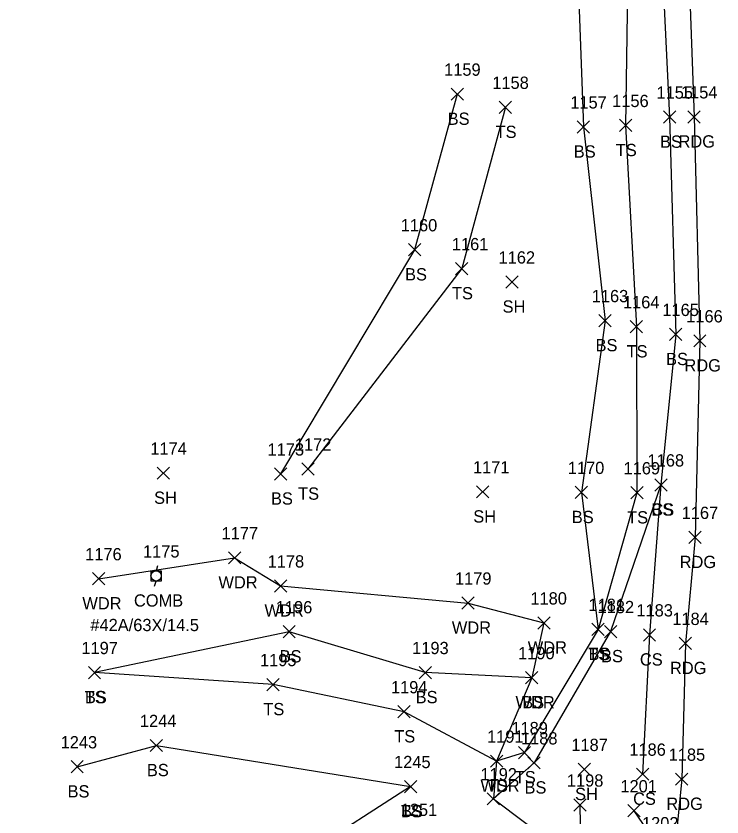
# Model space of a CAD drawing. Extents: x 1678553 to 1680768, y 787260 to 792325.
# Drawn here: x 1678586 to 1678701.1, y 787588.2 to 787718.8 of the extents above; entities that cross this region are included whole.
import ezdxf

# ---------------------------------------------------------------- set-up
doc = ezdxf.new("R2010")
doc.units = 0
for name, color, linetype in [('L_A', 7, 'Continuous'), ('L_I', 7, 'Continuous'), ('L_TIC', 7, 'Continuous'), ('LAWA', 7, 'Continuous'), ('LELB', 7, 'Continuous'), ('P_A', 7, 'Continuous'), ('P_I', 7, 'Continuous'), ('P_TIC', 7, 'Continuous'), ('PEU', 7, 'Continuous'), ('R_I', 7, 'Continuous'), ('R_TIC', 7, 'Continuous'), ('RGR', 7, 'Continuous'), ('U_A', 7, 'Continuous'), ('U_C', 7, 'Continuous'), ('U_I', 7, 'Continuous'), ('UP', 7, 'Continuous')]:
    doc.layers.add(name, color=color, linetype=linetype)

msp = doc.modelspace()

# ---------------------------------------------------------------- linework, layer by layer
at = {"layer": 'L_TIC'}
for points in [[(1678656.91, 787705.05), (1678658.91, 787707.05)], [(1678658.91, 787705.05), (1678656.91, 787707.05)], [(1678664.76, 787702.91), (1678666.76, 787704.91)], [(1678666.76, 787702.91), (1678664.76, 787704.91)], [(1678691.52, 787701.31), (1678693.52, 787703.31)], [(1678693.52, 787701.31), (1678691.52, 787703.31)], [(1678677.47, 787699.71), (1678679.47, 787701.71)], [(1678679.47, 787699.71), (1678677.47, 787701.71)], [(1678684.35, 787699.95), (1678686.35, 787701.95)], [(1678686.35, 787699.95), (1678684.35, 787701.95)], [(1678649.97, 787679.69), (1678651.97, 787681.69)], [(1678651.97, 787679.69), (1678649.97, 787681.69)], [(1678657.65, 787676.61), (1678659.65, 787678.61)], [(1678659.65, 787676.61), (1678657.65, 787678.61)], [(1678665.82, 787674.44), (1678667.82, 787676.44)], [(1678667.82, 787674.44), (1678665.82, 787676.44)], [(1678681.02, 787668.14), (1678683.02, 787670.14)], [(1678683.02, 787668.14), (1678681.02, 787670.14)], [(1678686.11, 787667.14), (1678688.11, 787669.14)], [(1678688.11, 787667.14), (1678686.11, 787669.14)], [(1678692.52, 787665.89), (1678694.52, 787667.89)], [(1678694.52, 787665.89), (1678692.52, 787667.89)], [(1678609.02, 787643.28), (1678611.02, 787645.28)], [(1678611.02, 787643.28), (1678609.02, 787645.28)], [(1678628.12, 787643.15), (1678630.12, 787645.15)], [(1678630.12, 787643.15), (1678628.12, 787645.15)], [(1678632.57, 787643.95), (1678634.57, 787645.95)], [(1678634.57, 787643.95), (1678632.57, 787645.95)], [(1678690.12, 787641.36), (1678692.12, 787643.36)], [(1678692.12, 787641.36), (1678690.12, 787643.36)], [(1678690.12, 787641.36), (1678692.12, 787643.36)], [(1678692.12, 787641.36), (1678690.12, 787643.36)], [(1678661.04, 787640.23), (1678663.04, 787642.23)], [(1678663.04, 787640.23), (1678661.04, 787642.23)], [(1678677.15, 787640.14), (1678679.15, 787642.14)], [(1678679.15, 787640.14), (1678677.15, 787642.14)], [(1678686.2, 787640.08), (1678688.2, 787642.08)], [(1678688.2, 787640.08), (1678686.2, 787642.08)], [(1678620.63, 787629.48), (1678622.63, 787631.48)], [(1678622.63, 787629.48), (1678620.63, 787631.48)], [(1678598.45, 787626.07), (1678600.45, 787628.07)], [(1678600.45, 787626.07), (1678598.45, 787628.07)], [(1678628.13, 787624.9), (1678630.13, 787626.9)], [(1678630.13, 787624.9), (1678628.13, 787626.9)], [(1678658.68, 787622.11), (1678660.68, 787624.11)], [(1678660.68, 787622.11), (1678658.68, 787624.11)], [(1678671.05, 787618.87), (1678673.05, 787620.87)], [(1678673.05, 787618.87), (1678671.05, 787620.87)], [(1678629.52, 787617.43), (1678631.52, 787619.43)], [(1678631.52, 787617.43), (1678629.52, 787619.43)], [(1678679.87, 787617.81), (1678681.87, 787619.81)], [(1678681.87, 787617.81), (1678679.87, 787619.81)], [(1678679.87, 787617.81), (1678681.87, 787619.81)], [(1678681.87, 787617.81), (1678679.87, 787619.81)], [(1678681.92, 787617.46), (1678683.92, 787619.46)], [(1678683.92, 787617.46), (1678681.92, 787619.46)], [(1678688.25, 787616.92), (1678690.25, 787618.92)], [(1678690.25, 787616.92), (1678688.25, 787618.92)], [(1678597.79, 787610.78), (1678599.79, 787612.78)], [(1678599.79, 787610.78), (1678597.79, 787612.78)], [(1678597.79, 787610.78), (1678599.79, 787612.78)], [(1678599.79, 787610.78), (1678597.79, 787612.78)], [(1678651.7, 787610.78), (1678653.7, 787612.78)], [(1678653.7, 787610.78), (1678651.7, 787612.78)], [(1678669.06, 787609.94), (1678671.06, 787611.94)], [(1678671.06, 787609.94), (1678669.06, 787611.94)], [(1678669.06, 787609.94), (1678671.06, 787611.94)], [(1678671.06, 787609.94), (1678669.06, 787611.94)], [(1678626.9, 787608.82), (1678628.9, 787610.82)], [(1678628.9, 787608.82), (1678626.9, 787610.82)], [(1678648.24, 787604.39), (1678650.24, 787606.39)], [(1678650.24, 787604.39), (1678648.24, 787606.39)], [(1678607.89, 787598.89), (1678609.89, 787600.89)], [(1678609.89, 787598.89), (1678607.89, 787600.89)], [(1678667.88, 787597.73), (1678669.88, 787599.73)], [(1678669.88, 787597.73), (1678667.88, 787599.73)], [(1678663.34, 787596.34), (1678665.34, 787598.34)], [(1678665.34, 787596.34), (1678663.34, 787598.34)], [(1678663.34, 787596.34), (1678665.34, 787598.34)], [(1678665.34, 787596.34), (1678663.34, 787598.34)], [(1678669.44, 787596.06), (1678671.44, 787598.06)], [(1678671.44, 787596.06), (1678669.44, 787598.06)], [(1678594.96, 787595.42), (1678596.96, 787597.42)], [(1678596.96, 787595.42), (1678594.96, 787597.42)], [(1678677.63, 787594.99), (1678679.63, 787596.99)], [(1678679.63, 787594.99), (1678677.63, 787596.99)], [(1678687.14, 787594.22), (1678689.14, 787596.22)], [(1678689.14, 787594.22), (1678687.14, 787596.22)], [(1678649.31, 787592.2), (1678651.31, 787594.2)], [(1678651.31, 787592.2), (1678649.31, 787594.2)], [(1678649.31, 787592.2), (1678651.31, 787594.2)], [(1678651.31, 787592.2), (1678649.31, 787594.2)], [(1678662.82, 787590.2), (1678664.82, 787592.2)], [(1678664.82, 787590.2), (1678662.82, 787592.2)], [(1678662.82, 787590.2), (1678664.82, 787592.2)], [(1678664.82, 787590.2), (1678662.82, 787592.2)], [(1678676.92, 787589.19), (1678678.92, 787591.19)], [(1678678.92, 787589.19), (1678676.92, 787591.19)]]:
    msp.add_lwpolyline(points, dxfattribs=at)
at = {"layer": 'LAWA'}
msp.add_lwpolyline([(1678599.45, 787627.07), (1678621.63, 787630.48), (1678629.13, 787625.9), (1678659.68, 787623.11), (1678672.05, 787619.87), (1678670.06, 787610.94), (1678664.34, 787597.34), (1678663.82, 787591.2), (1678674.57, 787583.12), (1678678.14, 787577.87), (1678672.71, 787567.7), (1678658.82, 787557.15), (1678637.9, 787553.69), (1678611.83, 787542.76), (1678587.07, 787526.57)], dxfattribs=at)
at = {"layer": 'LELB'}
for points in [[(1678682.79, 787833.91), (1678680.06, 787797.95), (1678684.41, 787774.01), (1678685.93, 787741.44), (1678685.35, 787700.95), (1678687.11, 787668.14), (1678687.2, 787641.08), (1678680.87, 787618.81), (1678668.88, 787598.73), (1678664.34, 787597.34), (1678649.24, 787605.39), (1678627.9, 787609.82), (1678598.79, 787611.78)], [(1678679.85, 787777.76), (1678676.94, 787743.26), (1678678.47, 787700.71), (1678682.02, 787669.14), (1678678.15, 787641.14), (1678680.87, 787618.81)], [(1678688.43, 787773.81), (1678690.64, 787740.5), (1678692.52, 787702.31), (1678693.52, 787666.89), (1678691.12, 787642.36), (1678682.92, 787618.46), (1678670.44, 787597.06), (1678663.82, 787591.2)], [(1678657.91, 787706.05), (1678650.97, 787680.69), (1678629.12, 787644.15)], [(1678665.76, 787703.91), (1678658.65, 787677.61), (1678633.57, 787644.95)], [(1678691.12, 787642.36), (1678689.25, 787617.92), (1678688.14, 787595.22)], [(1678670.06, 787610.94), (1678652.7, 787611.78), (1678630.52, 787618.43), (1678598.79, 787611.78)], [(1678595.96, 787596.42), (1678608.89, 787599.89), (1678650.31, 787593.2)], [(1678650.31, 787593.2), (1678633.3, 787582.25), (1678625.84, 787572.53), (1678610.05, 787567.92), (1678586, 787548.35)], [(1678677.92, 787590.19), (1678678.14, 787577.87), (1678684.37, 787570.24), (1678686.4, 787565.08)]]:
    msp.add_lwpolyline(points, dxfattribs=at)
at = {"layer": 'P_TIC'}
for points in [[(1678695.51, 787701.35), (1678697.51, 787703.35)], [(1678697.51, 787701.35), (1678695.51, 787703.35)], [(1678696.46, 787664.85), (1678698.46, 787666.85)], [(1678698.46, 787664.85), (1678696.46, 787666.85)], [(1678695.68, 787632.81), (1678697.68, 787634.81)], [(1678697.68, 787632.81), (1678695.68, 787634.81)], [(1678694.1, 787615.53), (1678696.1, 787617.53)], [(1678696.1, 787615.53), (1678694.1, 787617.53)], [(1678693.51, 787593.4), (1678695.51, 787595.4)], [(1678695.51, 787593.4), (1678693.51, 787595.4)]]:
    msp.add_lwpolyline(points, dxfattribs=at)
at = {"layer": 'PEU'}
msp.add_lwpolyline([(1678689.06, 787834.79), (1678688.67, 787796.64), (1678691.65, 787771.51), (1678695.2, 787739.73), (1678696.51, 787702.35), (1678697.46, 787665.85), (1678696.68, 787633.81), (1678695.1, 787616.53), (1678694.51, 787594.4), (1678691.17, 787560.92)], dxfattribs=at)
at = {"layer": 'R_TIC'}
for points in [[(1678685.71, 787588.25), (1678687.71, 787590.25)], [(1678687.71, 787588.25), (1678685.71, 787590.25)]]:
    msp.add_lwpolyline(points, dxfattribs=at)
at = {"layer": 'RGR'}
msp.add_lwpolyline([(1678686.71, 787589.25), (1678690.81, 787583.23), (1678691.72, 787577.16), (1678690.18, 787561.7)], dxfattribs=at)
at = {"layer": 'UP'}
for p, q in [((1678608, 787626.7), (1678608, 787628.37)), ((1678608, 787628.37), (1678609.66, 787628.37)), ((1678609.08, 787629.2), (1678608.83, 787628.37)), ((1678609.66, 787628.37), (1678609.66, 787626.7)), ((1678608.83, 787627.53), (1678608.83, 787627.53)), ((1678609.66, 787626.7), (1678608, 787626.7)), ((1678608.58, 787625.87), (1678608.83, 787626.7))]:
    msp.add_line(p, q, dxfattribs=at)
msp.add_circle((1678608.83, 787627.53), 0.833, dxfattribs=at)

# ---------------------------------------------------------------- texts
at = {"layer": 'L_A'}
for s, p in [('BS', (1678656.36, 787701.05)), ('TS', (1678664.17, 787698.91)), ('BS', (1678690.96, 787697.31)), ('BS', (1678676.91, 787695.71)), ('TS', (1678683.76, 787695.95)), ('BS', (1678649.41, 787675.69)), ('TS', (1678657.06, 787672.61)), ('SH', (1678665.31, 787670.44)), ('BS', (1678680.46, 787664.14)), ('TS', (1678685.52, 787663.14)), ('BS', (1678691.96, 787661.89)), ('SH', (1678608.5, 787639.28)), ('BS', (1678627.56, 787639.15)), ('TS', (1678631.98, 787639.95)), ('CS', (1678689.56, 787637.36)), ('BS', (1678689.56, 787637.36)), ('SH', (1678660.53, 787636.23)), ('BS', (1678676.59, 787636.14)), ('TS', (1678685.61, 787636.08)), ('WDR', (1678618.99, 787625.48)), ('WDR', (1678596.81, 787622.07)), ('WDR', (1678626.5, 787620.9)), ('WDR', (1678657.04, 787618.11)), ('WDR', (1678669.41, 787614.87)), ('BS', (1678628.96, 787613.43)), ('TS', (1678679.27, 787613.81)), ('BS', (1678679.31, 787613.81)), ('BS', (1678681.36, 787613.46)), ('CS', (1678687.69, 787612.92)), ('TS', (1678597.2, 787606.78)), ('BS', (1678597.23, 787606.78)), ('BS', (1678651.14, 787606.78)), ('WDR', (1678667.42, 787605.94)), ('BS', (1678668.5, 787605.94)), ('TS', (1678626.31, 787604.82)), ('TS', (1678647.65, 787600.39)), ('BS', (1678607.33, 787594.89)), ('TS', (1678667.29, 787593.73)), ('WDR', (1678661.7, 787592.34)), ('TS', (1678662.75, 787592.34)), ('BS', (1678668.88, 787592.06)), ('BS', (1678594.4, 787591.42)), ('SH', (1678677.12, 787590.99)), ('CS', (1678686.58, 787590.22)), ('TS', (1678648.72, 787588.2)), ('BS', (1678648.75, 787588.2))]:
    msp.add_text(s, height=2, dxfattribs=at).set_placement(p)
at = {"layer": 'L_I'}
for s, p in [('1159', (1678655.78, 787709.05)), ('1158', (1678663.63, 787706.91)), ('1155', (1678690.39, 787705.31)), ('1157', (1678676.34, 787703.71)), ('1156', (1678683.17, 787703.95)), ('1160', (1678648.71, 787683.69)), ('1161', (1678657.04, 787680.61)), ('1162', (1678664.65, 787678.44)), ('1163', (1678679.84, 787672.14)), ('1164', (1678684.93, 787671.14)), ('1165', (1678691.35, 787669.89)), ('1174', (1678607.89, 787647.28)), ('1173', (1678627, 787647.15)), ('1172', (1678631.45, 787647.95)), ('1168', (1678688.94, 787645.36)), ('1168', (1678688.94, 787645.36)), ('1171', (1678660.48, 787644.23)), ('1170', (1678675.94, 787644.14)), ('1169', (1678685.02, 787644.08)), ('1177', (1678619.5, 787633.48)), ('1176', (1678597.27, 787630.07)), ('1178', (1678627.01, 787628.9)), ('1179', (1678657.55, 787626.11)), ('1180', (1678669.84, 787622.87)), ('1196', (1678628.34, 787621.43)), ('1181', (1678679.31, 787621.81)), ('1181', (1678679.31, 787621.81)), ('1182', (1678680.79, 787621.46)), ('1183', (1678687.12, 787620.92)), ('1197', (1678596.66, 787614.78)), ('1197', (1678596.66, 787614.78)), ('1193', (1678650.57, 787614.78)), ('1190', (1678667.84, 787613.94)), ('1190', (1678667.84, 787613.94)), ('1195', (1678625.77, 787612.82)), ('1194', (1678647.11, 787608.39)), ('1244', (1678606.19, 787602.89)), ('1189', (1678666.74, 787601.73)), ('1191', (1678662.78, 787600.34)), ('1191', (1678662.78, 787600.34)), ('1188', (1678668.31, 787600.06)), ('1243', (1678593.27, 787599.42)), ('1187', (1678676.51, 787598.99)), ('1186', (1678685.96, 787598.22)), ('1245', (1678647.62, 787596.2)), ('1245', (1678647.62, 787596.2)), ('1192', (1678661.7, 787594.2)), ('1192', (1678661.7, 787594.2)), ('1198', (1678675.79, 787593.19)), ('1251', (1678648.7, 787588.41))]:
    msp.add_text(s, height=2, dxfattribs=at).set_placement(p)
at = {"layer": 'P_A'}
for p in [(1678693.99, 787697.35), (1678694.95, 787660.85), (1678694.17, 787628.81), (1678692.59, 787611.53), (1678692, 787589.4)]:
    msp.add_text('RDG', height=2, dxfattribs=at).set_placement(p)
at = {"layer": 'P_I'}
for s, p in [('1154', (1678694.38, 787705.35)), ('1166', (1678695.24, 787668.85)), ('1167', (1678694.5, 787636.81)), ('1184', (1678692.97, 787619.53)), ('1185', (1678692.38, 787597.4))]:
    msp.add_text(s, height=2, dxfattribs=at).set_placement(p)
at = {"layer": 'R_I'}
for s, p in [('1201', (1678684.51, 787592.25)), ('1202', (1678688.03, 787586.23))]:
    msp.add_text(s, height=2, dxfattribs=at).set_placement(p)
at = {"layer": 'U_A'}
msp.add_text('COMB', height=2, dxfattribs=at).set_placement((1678605.22, 787622.53))
at = {"layer": 'U_C'}
msp.add_text('#42A/63X/14.5', height=2, dxfattribs=at).set_placement((1678598.12, 787618.53))
at = {"layer": 'U_I'}
msp.add_text('1175', height=2, dxfattribs=at).set_placement((1678606.7, 787630.53))

doc.saveas('drawing.dxf')
